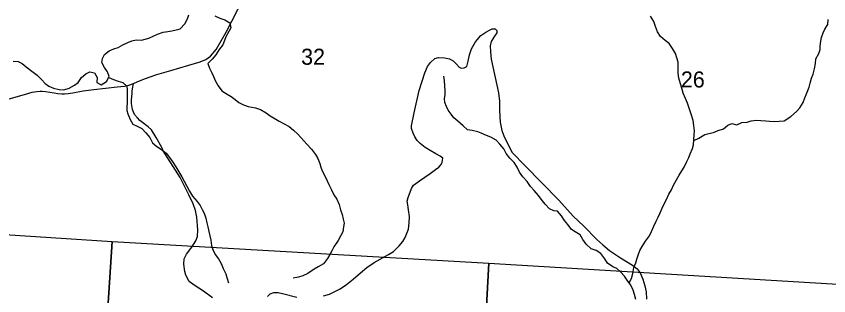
# Model space of a CAD drawing. Extents: x 0 to 34, y 0 to 22.
# Drawn here: x 26.642 to 28.762, y 19.835 to 20.563 of the extents above; entities that cross this region are included whole.
import ezdxf

# ---------------------------------------------------------------- set-up
doc = ezdxf.new("R2010")
doc.units = 0
for name, color, linetype in [('GM_X_County_Road', 7, 'Continuous'), ('GM_X_Major_River', 7, 'Continuous'), ('GM_X_Minor_River', 7, 'Continuous'), ('GM_X_Section', 7, 'Continuous'), ('GM_X_Section_Text', 7, 'Continuous'), ('GM_X_State_Route', 7, 'Continuous'), ('GM_X_Township_Road', 7, 'Continuous')]:
    doc.layers.add(name, color=color, linetype=linetype)

msp = doc.modelspace()

# ---------------------------------------------------------------- linework, layer by layer
at = {"layer": 'GM_X_County_Road'}
msp.add_lwpolyline([(27.1544, 19.8297), (27.1312, 19.8465), (27.1067, 19.8621), (27.0939, 19.8716), (27.085, 19.8884), (27.0821, 19.8982), (27.0795, 19.9168), (27.0804, 19.9306), (27.087, 19.9431), (27.1005, 19.961), (27.1113, 19.9781), (27.1156, 19.989), (27.1165, 20.0068), (27.1135, 20.0398), (27.1104, 20.0569), (27.104, 20.0741), (27.0927, 20.0976), (27.07, 20.1426), (27.026, 20.2129), (27.022, 20.2215), (27.0073, 20.2475), (26.9954, 20.2668), (26.9868, 20.275), (26.9645, 20.2919), (26.959, 20.2983), (26.951, 20.3074), (26.9458, 20.32), (26.9428, 20.3359), (26.9432, 20.3453), (26.9446, 20.3616), (26.9452, 20.3683), (26.9461, 20.3738), (26.9486, 20.3879)], dxfattribs=at)
at = {"layer": 'GM_X_Major_River'}
for points in [[(26.7275, 20.3814), (26.7396, 20.3756), (26.7544, 20.372), (26.7661, 20.3716), (26.7806, 20.3757), (26.7947, 20.3835), (26.8042, 20.391), (26.813, 20.4039), (26.8241, 20.4133), (26.8344, 20.4181), (26.8469, 20.4161), (26.8536, 20.4036), (26.8528, 20.3907), (26.8641, 20.3845), (26.8778, 20.3928), (26.8851, 20.406), (26.8806, 20.4185), (26.8724, 20.4296), (26.866, 20.4429), (26.8672, 20.4535), (26.8722, 20.4634), (26.8844, 20.4735), (26.897, 20.4783), (26.908, 20.4821), (26.9205, 20.4892), (26.9331, 20.4951), (26.9441, 20.4996), (26.9552, 20.5018), (26.9692, 20.5013), (26.9791, 20.5032), (26.9886, 20.5061), (26.9992, 20.511), (27.0106, 20.5162), (27.0255, 20.5214), (27.0376, 20.5232), (27.0482, 20.5254), (27.06, 20.5276), (27.0703, 20.5309), (27.0821, 20.5434), (27.089, 20.5566), (27.0929, 20.5668)], [(26.6343, 20.4465), (26.6475, 20.4449), (26.6577, 20.4403), (26.6683, 20.4315), (26.6834, 20.4204), (26.697, 20.4093), (26.7083, 20.3982), (26.7177, 20.3883), (26.7275, 20.3814)]]:
    msp.add_lwpolyline(points, dxfattribs=at)
at = {"layer": 'GM_X_Minor_River'}
for points in [[(27.1602, 20.5646), (27.1739, 20.5582), (27.1868, 20.5537), (27.1993, 20.5458), (27.202, 20.5329), (27.1971, 20.5234), (27.1896, 20.5097), (27.1854, 20.4998), (27.1813, 20.4892), (27.1715, 20.4763), (27.1628, 20.463), (27.1534, 20.4512), (27.1421, 20.4398), (27.1467, 20.4281), (27.1531, 20.416), (27.1566, 20.4061), (27.1619, 20.394), (27.1691, 20.3819), (27.179, 20.369), (27.1931, 20.3604), (27.2033, 20.3539), (27.2135, 20.3464), (27.223, 20.3388), (27.2352, 20.3324), (27.2473, 20.3279), (27.2568, 20.326), (27.267, 20.3249), (27.2795, 20.32), (27.2943, 20.3113), (27.3049, 20.3041), (27.3155, 20.2973), (27.3284, 20.2898), (27.3413, 20.283), (27.3542, 20.2755), (27.3656, 20.2664), (27.3774, 20.2558), (27.4009, 20.2301), (27.4127, 20.2168), (27.423, 20.2032), (27.4294, 20.1922), (27.4344, 20.1797), (27.4371, 20.1703), (27.4409, 20.16), (27.4481, 20.146), (27.4538, 20.1347), (27.458, 20.1244), (27.4645, 20.1108), (27.4714, 20.0976), (27.479, 20.0862), (27.4847, 20.073), (27.4881, 20.0589), (27.4924, 20.0464), (27.4954, 20.0343), (27.4977, 20.0241), (27.4959, 20.0146), (27.4944, 20.0017), (27.4891, 19.9922), (27.482, 19.9786), (27.471, 19.9626), (27.4658, 19.9516), (27.4609, 19.9421), (27.4545, 19.9315), (27.4439, 19.9182), (27.43, 19.9102), (27.4198, 19.9037), (27.4035, 19.8931), (27.3899, 19.887), (27.3786, 19.8832), (27.3653, 19.8805)], [(28.2419, 19.8681), (28.2477, 19.88), (28.2507, 19.8925), (28.2533, 19.908), (28.2585, 19.9206), (28.2619, 19.9301), (28.2653, 19.9407), (28.269, 19.9528), (28.2758, 19.9634), (28.2841, 19.9771), (28.2943, 19.9908), (28.2995, 20.0018), (28.3056, 20.0158), (28.3119, 20.0291), (28.3168, 20.0397), (28.3225, 20.0507), (28.3274, 20.0633), (28.3326, 20.0743), (28.3386, 20.0857), (28.3454, 20.0993), (28.3518, 20.1111), (28.3567, 20.121), (28.3654, 20.1365), (28.3721, 20.1487), (28.3793, 20.1601), (28.3853, 20.1699), (28.3921, 20.1843), (28.3973, 20.195), (28.4003, 20.2048), (28.4064, 20.2189), (28.409, 20.2284), (28.4104, 20.2413), (28.4115, 20.2545), (28.4119, 20.2644), (28.4103, 20.2784), (28.4084, 20.2913), (28.4046, 20.3053), (28.4004, 20.3159), (28.3969, 20.3261), (28.3939, 20.3364), (28.3885, 20.3485), (28.3824, 20.3625), (28.3786, 20.3758), (28.3755, 20.3867), (28.3709, 20.4019), (28.3694, 20.4152), (28.3693, 20.4432), (28.3662, 20.455), (28.362, 20.4663), (28.3544, 20.4792), (28.346, 20.4924), (28.3358, 20.5004), (28.3229, 20.5102), (28.3157, 20.5227), (28.3103, 20.5363), (28.3061, 20.5492), (28.297, 20.5636)], [(28.6635, 20.3024), (28.6783, 20.315), (28.687, 20.3249), (28.6953, 20.3382), (28.7002, 20.3503), (28.7044, 20.3609), (28.7112, 20.3788), (28.7142, 20.389), (28.7172, 20.4019), (28.7214, 20.4121), (28.7255, 20.4266), (28.7274, 20.4398), (28.7285, 20.4523), (28.7365, 20.4664), (28.7395, 20.4762), (28.7402, 20.4857), (28.7413, 20.4982), (28.7432, 20.5077), (28.7481, 20.5199), (28.7523, 20.5293), (28.7602, 20.5422), (28.761, 20.5548)], [(26.8839, 20.4038), (26.8965, 20.3987), (26.9083, 20.3945), (26.9204, 20.3904), (26.9307, 20.381), (26.9322, 20.3715), (26.9322, 20.362), (26.9319, 20.3506), (26.9316, 20.337), (26.9308, 20.3275), (26.9309, 20.318), (26.9339, 20.3085), (26.9396, 20.2942), (26.9465, 20.2817), (26.9575, 20.2768), (26.9696, 20.2707), (26.9806, 20.2594), (26.9905, 20.2469), (26.9978, 20.2336), (27.0091, 20.2238), (27.0217, 20.2159), (27.0334, 20.2068), (27.0418, 20.1951), (27.0505, 20.1826), (27.0585, 20.1709), (27.0665, 20.1576), (27.0745, 20.1451), (27.0806, 20.1334), (27.0875, 20.1201), (27.0943, 20.1076), (27.1023, 20.094), (27.1141, 20.0804), (27.1221, 20.0698), (27.1274, 20.06), (27.1323, 20.0501), (27.1369, 20.0369), (27.1392, 20.0251), (27.1423, 20.0141), (27.145, 20.002), (27.1477, 19.9906), (27.15, 19.9796), (27.1519, 19.9656), (27.1554, 19.9554), (27.1611, 19.9425), (27.1698, 19.9308), (27.1774, 19.9187), (27.1824, 19.9062), (27.1889, 19.8922), (27.1919, 19.8823), (27.1958, 19.8683)], [(27.7604, 20.3807), (27.7596, 20.3955), (27.7577, 20.4068)], [(28.2588, 19.825), (28.2554, 19.8379), (28.2523, 19.8489), (28.2462, 19.8622), (28.2363, 19.8758), (28.2291, 19.8856), (28.2189, 19.8973), (28.2094, 19.9057), (28.1991, 19.9098), (28.1847, 19.9193), (28.1779, 19.9314), (28.1672, 19.9446), (28.1551, 19.9525), (28.1426, 19.9571), (28.1293, 19.9688), (28.1209, 19.9816), (28.1133, 19.9938), (28.1008, 20.0013), (28.0913, 20.0073), (28.0814, 20.0202), (28.0731, 20.0312), (28.0651, 20.0429), (28.0545, 20.055), (28.0446, 20.0565), (28.0336, 20.061), (28.0226, 20.0735), (28.0116, 20.0864), (28.0047, 20.0962), (27.9933, 20.1091), (27.9838, 20.1193), (27.9751, 20.1322), (27.9645, 20.145), (27.9553, 20.1567), (27.9489, 20.17), (27.9416, 20.1817), (27.9306, 20.1938), (27.9207, 20.2059), (27.9143, 20.2173), (27.9044, 20.2298), (27.8941, 20.24), (27.8808, 20.2479), (27.8691, 20.2528), (27.8558, 20.2585), (27.8464, 20.2619), (27.832, 20.2656), (27.8198, 20.2671), (27.8081, 20.2777), (27.7944, 20.2898), (27.7845, 20.2985), (27.7773, 20.3083), (27.7693, 20.3182), (27.7648, 20.328), (27.7606, 20.3386), (27.7601, 20.3485), (27.7613, 20.3583), (27.7612, 20.3697), (27.7604, 20.3807)], [(28.4102, 20.239), (28.4237, 20.2455), (28.4392, 20.255), (28.449, 20.2573), (28.4615, 20.2607), (28.474, 20.2657), (28.4876, 20.2695), (28.4989, 20.2794), (28.5091, 20.284), (28.5224, 20.2806), (28.5352, 20.2859), (28.5496, 20.2875), (28.5598, 20.2909), (28.5738, 20.2921), (28.5852, 20.2913), (28.5977, 20.291), (28.6075, 20.2899), (28.6204, 20.2888), (28.6329, 20.2896), (28.6457, 20.2911), (28.6635, 20.3024)]]:
    msp.add_lwpolyline(points, dxfattribs=at)
at = {"layer": 'GM_X_Section'}
for points in [[(25.8788, 20.042), (26.893, 19.9764), (26.8274, 18.9732), (25.8109, 19.0399)], [(27.875, 19.9199), (27.8204, 18.905), (26.8274, 18.9732), (26.893, 19.9764)], [(27.875, 19.9199), (28.8721, 19.8598), (28.7909, 18.8364), (27.8204, 18.905)]]:
    msp.add_lwpolyline(points, close=True, dxfattribs=at)
at = {"layer": 'GM_X_State_Route'}
for points in [[(26.9486, 20.3879), (26.9578, 20.3922), (26.9773, 20.4004), (27.0092, 20.4114), (27.0394, 20.42), (27.0459, 20.4218), (27.093, 20.4356), (27.1223, 20.4445), (27.1367, 20.4506), (27.1489, 20.4589), (27.1642, 20.4763), (27.1899, 20.522), (27.2352, 20.61)], [(26.4629, 20.312), (26.4806, 20.3147), (26.5236, 20.323), (26.5926, 20.3391), (26.6637, 20.3594), (26.6835, 20.3651), (26.6957, 20.3672), (26.7046, 20.3676), (26.7099, 20.3676), (26.7191, 20.3674), (26.741, 20.3637), (26.7513, 20.3623), (26.761, 20.361), (26.7679, 20.3614), (26.7776, 20.3623), (26.7902, 20.3637), (26.8171, 20.3686), (26.8445, 20.3725), (26.9058, 20.3793), (26.9246, 20.3812), (26.9361, 20.3835), (26.9486, 20.3879)]]:
    msp.add_lwpolyline(points, dxfattribs=at)
at = {"layer": 'GM_X_Township_Road'}
for points in [[(27.4438, 19.8343), (27.4597, 19.8392), (27.4732, 19.8456), (27.4872, 19.8532), (27.5041, 19.8639), (27.5215, 19.878), (27.5402, 19.8942), (27.5573, 19.908), (27.5766, 19.9214), (27.6139, 19.9422), (27.6264, 19.9502), (27.6356, 19.9584), (27.6414, 19.9649), (27.6508, 19.9759), (27.6574, 19.9865), (27.6605, 19.995), (27.6659, 20.0086), (27.6677, 20.0251), (27.6686, 20.0416), (27.6656, 20.0588), (27.6637, 20.0713), (27.662, 20.0812), (27.6653, 20.0909), (27.6732, 20.1141), (27.679, 20.1227), (27.6943, 20.1346), (27.7225, 20.153), (27.7359, 20.164), (27.7448, 20.1701), (27.7513, 20.1765), (27.7534, 20.183), (27.7555, 20.1931), (27.7488, 20.1986), (27.7371, 20.205), (27.7225, 20.2135), (27.709, 20.2215), (27.6965, 20.2313), (27.6885, 20.2395), (27.6827, 20.2493), (27.6781, 20.2588), (27.6738, 20.2707), (27.6735, 20.2775), (27.6809, 20.3117), (27.694, 20.3695), (27.7084, 20.4157), (27.7157, 20.4323), (27.7233, 20.4428), (27.7347, 20.4534), (27.7445, 20.4555), (27.7595, 20.4546), (27.7726, 20.4521), (27.7827, 20.4469), (27.791, 20.4387), (27.798, 20.4307), (27.8029, 20.428), (27.8109, 20.4289), (27.8176, 20.4323), (27.8219, 20.446), (27.8252, 20.4631), (27.8304, 20.4787), (27.8405, 20.4965), (27.8544, 20.5132), (27.8677, 20.5216), (27.8775, 20.5268), (27.8843, 20.5304), (27.8922, 20.5304), (27.8962, 20.5262), (27.8959, 20.52), (27.8898, 20.5115), (27.8819, 20.4974), (27.8791, 20.4858), (27.88, 20.4708), (27.8815, 20.4512), (27.9005, 20.3634), (27.9029, 20.3423), (27.9035, 20.3172), (27.9051, 20.287), (27.909, 20.2655), (27.9145, 20.2512), (27.9259, 20.2285), (27.9364, 20.2082), (27.9701, 20.1736), (28.058, 20.0835), (28.0956, 20.0426), (28.1232, 20.0163), (28.1571, 19.9814), (28.1724, 19.9679), (28.1898, 19.9529), (28.2192, 19.9337), (28.2504, 19.9141), (28.262, 19.9049), (28.2706, 19.8948), (28.2773, 19.8777), (28.2828, 19.8609), (28.2862, 19.845), (28.2868, 19.826)], [(27.2979, 19.833), (27.3052, 19.8398), (27.3144, 19.8428), (27.3254, 19.8434), (27.3371, 19.8407), (27.3741, 19.8312)]]:
    msp.add_lwpolyline(points, dxfattribs=at)

# ---------------------------------------------------------------- texts
at = {"layer": 'GM_X_Section_Text'}
for s, p in [('32', (27.3857, 20.4368)), ('26', (28.3765, 20.3776))]:
    msp.add_text(s, height=0.04186, rotation=0, dxfattribs=at).set_placement(p)

doc.saveas('drawing.dxf')
